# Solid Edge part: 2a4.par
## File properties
Author: edge
Template: jis part.par
Last saved by: edge
Revision: 21
Application: Solid Edge
Accuracy: 0.990
文書内容のタイプ: 0
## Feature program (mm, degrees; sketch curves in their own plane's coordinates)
sketch for "unnamed Protrusion 1" plane through (0, 0, 0) normal (1, 0, 0) x-axis (0, 1, 0)
  line (0, 0) -> (-80, 0)
  line (-80, 0) -> (-80, 180)
  line (-80, 180) -> (0, 180)
  line (0, 180) -> (0, 0)
extrude "unnamed Protrusion 1" add finite 160 symmetric
thinwall "Thinwall_1"  Thickness = 20 mm
sketch for "unnamed Cutout 1" plane through (0, 0, 0) normal (0, -1, 0) x-axis (1, 0, 0)
  circle centre (0, 120) radius 27.5
extrude "unnamed Cutout 1" cut through
sketch for "unnamed Cutout 2" #1 plane through (0, 0, 0) normal (0, -1, 0) x-axis (1, 0, 0)
sketch for "unnamed Cutout 2" #2 plane through (0, 0, 0) normal (0, -1, 0) x-axis (1, 0, 0)
  circle centre (-50, 120) radius 6
extrude "unnamed Cutout 2" cut through along +normal
sketch for "unnamed Cutout 3" #1 plane through (0, 0, 0) normal (0, 0, 1) x-axis (1, 0, 0)
sketch for "unnamed Cutout 3" #2 plane through (0, 0, 0) normal (0, 0, 1) x-axis (1, 0, 0)
extrude "unnamed Cutout 3" cut through along +normal
chamfer "Chamfer_1" setback 5
chamfer "Chamfer_2" setback 5
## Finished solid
Body 1: solid body, 17 faces, 40 edges, 20 vertices.
  Faces by surface: plane 12, cylinder 5
  Edges by curve: line 30, circle 10
Bounding box of the edges (mm): 160.000 x 80.000 x 180.000, from (-80, -80, 0) to (80, 0, 180).
Cylindrical faces by radius (mm): R6 x2, R7.5 x2, R27.5 x1
Planar faces by outward normal: +x 1, +y 1, +z 2, -x 1, -y 2, -z 1, oblique 4
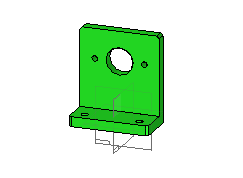
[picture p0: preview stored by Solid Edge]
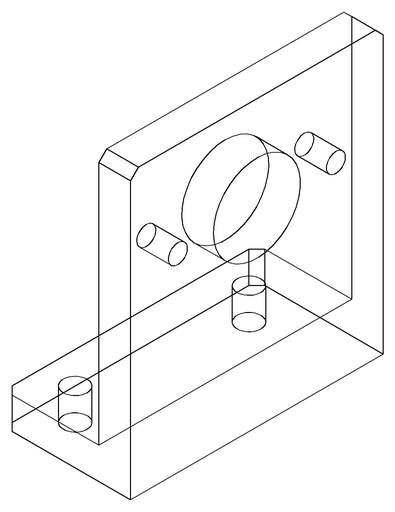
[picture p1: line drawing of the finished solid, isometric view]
